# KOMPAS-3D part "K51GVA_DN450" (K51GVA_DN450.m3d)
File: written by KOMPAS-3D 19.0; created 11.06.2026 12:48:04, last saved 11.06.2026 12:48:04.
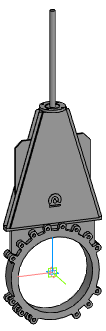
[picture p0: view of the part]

Document properties: Автор: Энергия; Полное имя файла: Z:\3.Личные\kachalov\001_3d для проектировщиков\2.6 Тип_K51GVA. Задвижка\_stp\_stp_K51GVA_DN50-DN1000_с фланцем\K51GVA_DN450.m3d

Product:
- Part/product: K51GVA_DN450

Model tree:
1. Операция без истории:1  (labels: K51GVA_DN450)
